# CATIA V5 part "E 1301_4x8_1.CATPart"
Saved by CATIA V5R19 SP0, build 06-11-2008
Part number: E 1301_4x8_1
Definition: E 1301_4x8_1
Nomenclature: E 1301_4x8_1
Source: Unknown
Description: PART-E 1301_4x8_1-DESC
Bounding box of the stored display mesh (mm): x -2 to 2, y -2 to 2, z 0 to 8
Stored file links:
  C:\Users\jsmid\Desktop\DP_Smidak_Forma LEGO\E 1301_4x8_1.CATPart
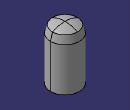
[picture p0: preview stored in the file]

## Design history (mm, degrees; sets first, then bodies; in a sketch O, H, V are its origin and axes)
Set1 "FaceKO#ADVANCED_FACE #75#75"
  DatumSurface1 "Sur75_1"
  Circle1 "Crv75_1": stored without definition
  Circle2 "Crv75_1": stored without definition
  DatumCurve1 "PCrv75_1"
  DatumCurve2 "PCrv75_2"
  DatumCurve3 "PCrv75_3"
  DatumCurve4 "PCrv75_4"
  DatumCurve5 "PCrv75_5"
Set2
  DatumSurface2 "CLOSED_SHELL #110"
Body1 (main body)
